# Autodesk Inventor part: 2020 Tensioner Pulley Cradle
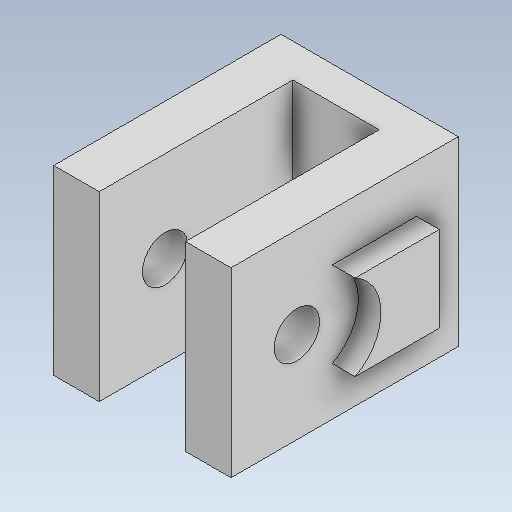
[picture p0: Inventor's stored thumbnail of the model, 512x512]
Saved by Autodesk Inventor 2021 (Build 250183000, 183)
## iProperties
Created: 2023-10
Part Number: 2020 Tensioner Pulley Cradle
Material: Generico
Document SubType Name: Modeling
Designer: hp
Density: 1 g/cm^3
Appearance: Default
Author: hp
Revision Number: ANY
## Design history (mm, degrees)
feature "Solido1"
body "Solid1"
